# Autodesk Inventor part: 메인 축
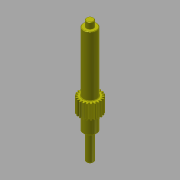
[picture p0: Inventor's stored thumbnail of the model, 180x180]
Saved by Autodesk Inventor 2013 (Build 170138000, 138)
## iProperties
Created: 2016-02
Part Number: 메인 축
Material: 강철, 연강
Document SubType Name: Modeling
Categories: <?xml version="1.0" encoding="UTF-16"?> <MemberInstance><Categories><FamilyTemplate><FamilyTemplateParameter ValueType="xs:double" Id="1" ObjectReferenceKey="da
Density: 7.86 g/cm^3
Mass: 187.503 g
Surface Area: 82.0529 cm^2
Volume: 23.8554 cm^3
Author: mdu
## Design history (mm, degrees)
sketch "Sketch1"
  geometry: C1 r 12 at (0, 0)
  constraints: 1 centre point
  dimensions: "d0" = 24 diameter of C1 (= da_da)
extrude "Extrusion1" new body sketch "Sketch1" distance "d1" = 20 (= da_b); taper "d2" = 0 deg
workplane "Work Plane2"
feature "피치 지름" dims "d4" = 10, "d5" = 0
workplane "Work Plane8"
workplane "Work Plane9"
chamfer "모따기1" distance "d49" = 1; stored, may be unused: second distance "d50" = 2, angle "d51" = 45 deg
sketch "스케치3"
  geometry: C1 r 7.5 at (0, 0); 1 further point
  constraints: 1 centre point, 1 coincident
  dimensions: "d52" = 15 diameter of C1
extrude "돌출2" join sketch "스케치3" distance "d53" = 66; taper "d54" = 0 deg
sketch "스케치4"
  geometry: C1 r 4 at (0, 0); 1 further point
  constraints: 1 centre point, 1 coincident
  dimensions: "d55" = 8 diameter of C1
extrude "돌출3" join sketch "스케치4" distance "d56" = 7; taper "d57" = 0 deg
sketch "스케치5"
  geometry: C1 r 7.5 at (0, 0) reference; C2 r 7.5 at (0, 0) reference; 1 further point
extrude "돌출4" join sketch "스케치5" distance "d62" = 16; taper "d63" = 0 deg
sketch "스케치6"
  geometry: C1 r 4 at (0, 0); 1 further point
  constraints: 1 centre point, 1 coincident
  dimensions: "d64" = 8 diameter of C1
extrude "돌출5" join sketch "스케치6" distance "d65" = 30; taper "d66" = 0 deg
chamfer "모따기2" distance "d58" = 0.5; stored, may be unused: second distance "d59" = 2, angle "d60" = 45 deg
fillet "모깎기1" dims "d61" = 0.5
feature "스퍼 기어" dims "da_b" = 20, "da_d" = 22, "da_aw" = 31, "da_da" = 24, "da_df" = 19.5, "da_dw" = 22, angle "da_beta" = 0 deg, "da_lefttooth" = 0, "da_righttooth" = 0
sketch "스케치7" dims "d68" = 18
  geometry: C1 r 0.25 at (0, -9); 2 further points
  constraints: 2 vertical alignment, 1 centre point, 1 coincident, 2 other
  dimensions: "d67" = 0.5 diameter of C1
extrude "돌출6" join sketch "스케치7" distance "d69" = 0.3; taper "d70" = 0 deg
feature "면 이동1"
feature "면 이동2"
feature "면 이동3"
body "Solid1"
sketch "Sketch2"
  geometry: C1 r 12 at (0, 0) reference; C2 r 11 at (0, 0)
  constraints: 1 centre point, 1 coincident
  dimensions: "d3" = 22 diameter of C2 (= da_dw)
body "Srf1"
node "투영된 루프1"
other parameters: "d16" = 31 (= da_aw), "d17" = 0, "d34" = 1.428 (computed from da_z), "d39" = 0, "d41" = 0, "d43" = 31 (= da_aw), "d46" = 31 (= da_aw), "d47" = 0, "d48" = 0
